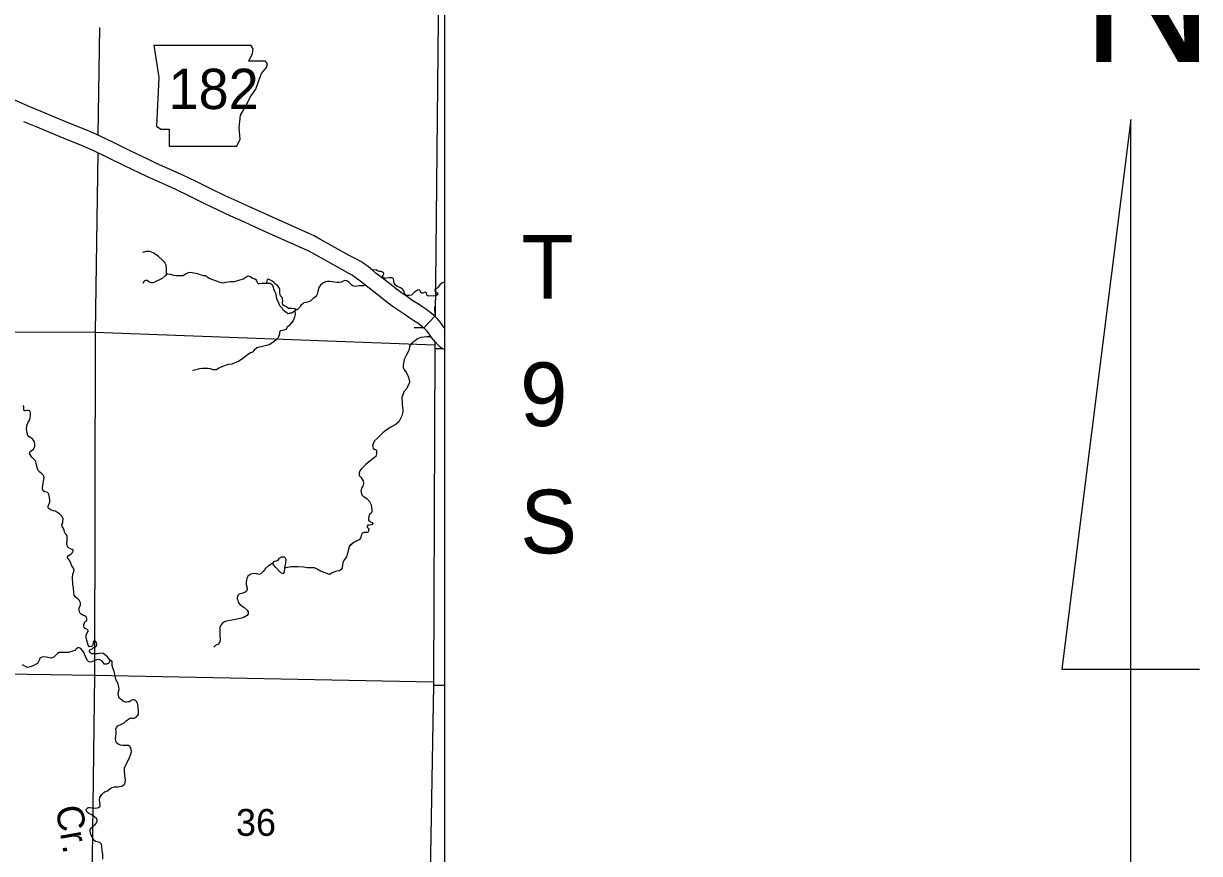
# Model space of a CAD drawing. Extents: x 8749 to 11879, y 13275 to 15339.
# Drawn here: x 10827.5 to 11197, y 14014.5 to 14275.3 of the extents above; entities that cross this region are included whole.
import ezdxf

# ---------------------------------------------------------------- set-up
doc = ezdxf.new("R2010")
doc.units = 0
for name, color, linetype in [('Level 10', 7, 'Continuous'), ('Level 21', 7, 'Continuous'), ('Level 35', 7, 'Continuous'), ('Level 37', 7, 'Continuous'), ('Level 4', 7, 'Continuous'), ('Level 5', 7, 'Continuous'), ('R_Draft', 7, 'Continuous')]:
    doc.layers.add(name, color=color, linetype=linetype)

msp = doc.modelspace()

# ---------------------------------------------------------------- linework, layer by layer
at = {"layer": 'Level 10'}
msp.add_line((10934.16, 14200.04), (10934.13, 14200.06), dxfattribs=at)
for points in [[(10829.51, 14249.1), (10825.17, 14251.01), (10819.52, 14253.48), (10816.27, 14255.03), (10810.76, 14257.54), (10799.85, 14262.61)], [(10934.13, 14200.06), (10933.48, 14200.51), (10932.12, 14201.21), (10929.79, 14202.45), (10925.33, 14204.94), (10920.85, 14207.48), (10918.81, 14208.61), (10916.91, 14209.41), (10909.69, 14212.62), (10905.7, 14214.42), (10902.28, 14215.98), (10898.66, 14217.62), (10894.6, 14219.43), (10890.89, 14221.18), (10886.09, 14223.48), (10881.79, 14225.62), (10877.39, 14227.73), (10872.88, 14229.79), (10869.32, 14231.35), (10866.32, 14232.74), (10861.04, 14235.3), (10856.14, 14237.66), (10851.37, 14240.02), (10847.57, 14241.67), (10842.09, 14243.9), (10837.58, 14245.78), (10833.04, 14247.62), (10829.46, 14249.12)], [(10827.53, 14244.51), (10831.14, 14243), (10835.68, 14241.16), (10840.18, 14239.28), (10845.63, 14237.06), (10849.27, 14235.49), (10853.95, 14233.17), (10858.86, 14230.8), (10864.18, 14228.23), (10867.26, 14226.79), (10870.83, 14225.22), (10875.27, 14223.2), (10879.59, 14221.12), (10883.9, 14218.99), (10888.74, 14216.66), (10892.52, 14214.88), (10896.61, 14213.05), (10900.22, 14211.42), (10903.63, 14209.87), (10907.65, 14208.06), (10914.92, 14204.82), (10916.62, 14204.1), (10918.4, 14203.12), (10922.88, 14200.58), (10927.4, 14198.06), (10929.8, 14196.78), (10930.91, 14196.21), (10931.29, 14195.94)], [(10956.72, 14183.3), (10955.56, 14184.31), (10954.24, 14185.31), (10952.92, 14186.19), (10951.63, 14187.06), (10949.82, 14188.2), (10948.1, 14189.39), (10946.28, 14190.68), (10944.68, 14191.87), (10943.02, 14193.14), (10941.63, 14194.24), (10940.7, 14195.02), (10939.07, 14196.23), (10938.34, 14196.78), (10937.26, 14197.69), (10936.41, 14198.38), (10935.46, 14199.12), (10934.16, 14200.04)], [(10931.27, 14195.96), (10932.47, 14195.11), (10933.3, 14194.46), (10934.07, 14193.84), (10935.21, 14192.87), (10936.07, 14192.22), (10937.59, 14191.09), (10938.47, 14190.36), (10939.95, 14189.19), (10941.68, 14187.87), (10943.34, 14186.63), (10945.23, 14185.29), (10947.06, 14184.03), (10948.9, 14182.86), (10950.14, 14182.03), (10951.34, 14181.24), (10953.25, 14179.7)], [(10953.25, 14179.7), (10956.72, 14183.3)], [(10959.72, 14179.64), (10959.71, 14179.65), (10958.83, 14180.88), (10958.19, 14181.72), (10957.48, 14182.57), (10956.72, 14183.3)], [(10959.72, 14172.87), (10959.26, 14173.09), (10958.31, 14173.75), (10957.84, 14174.15), (10956.91, 14175.14), (10955.73, 14176.62), (10954.81, 14177.9), (10954.27, 14178.6), (10953.81, 14179.16), (10953.25, 14179.7)]]:
    msp.add_lwpolyline(points, dxfattribs=at)
at = {"layer": 'Level 21'}
for p, q in [((10868.47, 14268.54), (10869.99, 14258.39)), ((10898.24, 14263.47), (10899.43, 14265.84)), ((10899.6, 14267.36), (10898.9, 14268.53)), ((10899.43, 14265.84), (10899.6, 14267.36)), ((10903.49, 14263.47), (10898.24, 14263.47)), ((10904.17, 14262.62), (10903.49, 14263.47)), ((10903.83, 14261.44), (10904.17, 14262.62)), ((10869.99, 14258.39), (10869.31, 14243)), ((10901.46, 14257.38), (10902.3, 14259.58)), ((10902.3, 14259.58), (10903.83, 14261.44)), ((10898.75, 14252.13), (10900.44, 14254.67)), ((10900.44, 14254.67), (10901.46, 14257.38)), ((10897.57, 14249.76), (10898.75, 14252.13)), ((10895.71, 14246.55), (10897.57, 14249.76)), ((10895.2, 14242.49), (10895.71, 14246.55)), ((10869.31, 14243), (10870.67, 14242.15)), ((10870.67, 14242.15), (10873.21, 14242.15)), ((10873.21, 14242.15), (10873.21, 14236.74)), ((10895.54, 14238.94), (10895.2, 14242.49)), ((10873.21, 14236.74), (10894.52, 14236.74)), ((10894.52, 14236.74), (10895.54, 14238.94))]:
    msp.add_line(p, q, dxfattribs=at)
msp.add_lwpolyline([(10868.47, 14268.54), (10898.9, 14268.53)], dxfattribs=at)
at = {"layer": 'Level 35'}
for points in [[(10872.4, 14196.52), (10872.45, 14197.58), (10872.47, 14198.44), (10872.35, 14199.32), (10871.89, 14200.2), (10871.34, 14200.76), (10869.88, 14202.09), (10868.27, 14203.28), (10867.23, 14203.68), (10866.07, 14203.63), (10864.89, 14203.35)], [(10881.66, 14196.7), (10880.44, 14197), (10879.86, 14197.02), (10879.18, 14196.97), (10878.34, 14196.49), (10877.69, 14196.06), (10876.33, 14196.01), (10875.42, 14196.04), (10874.72, 14196.14), (10873.66, 14196.47), (10872.85, 14196.54), (10872.4, 14196.52), (10871.97, 14196.01), (10871.11, 14195.16), (10870.26, 14194.73), (10869.45, 14194.4), (10868.27, 14193.85), (10867.61, 14193.85), (10866.86, 14194.17), (10866.35, 14194.53), (10865.82, 14194.58), (10865.37, 14194.35), (10864.97, 14193.59)], [(10896.5, 14194.99), (10895.02, 14194.6), (10893.71, 14194.17), (10892.55, 14194.1), (10891.67, 14194.05), (10890.88, 14193.95), (10890.1, 14193.74), (10889.25, 14193.9), (10886.95, 14194.73), (10885.87, 14195.13), (10885.47, 14195.36), (10885.04, 14195.81), (10884.69, 14195.99), (10884.06, 14196.06), (10883.3, 14196.27), (10882.27, 14196.62), (10881.66, 14196.7)], [(10914.46, 14186.52), (10914.19, 14186.04), (10913.81, 14185.66), (10913.43, 14185.36), (10913.2, 14185.33), (10912.77, 14185.66), (10911.79, 14185.74), (10910.78, 14185.79), (10910.1, 14186.24), (10909.6, 14186.52), (10909, 14186.9), (10908.87, 14187.58), (10908.94, 14188.31), (10908.77, 14189.17), (10908.26, 14189.77), (10908.04, 14190.58), (10908.04, 14191.16), (10908.06, 14191.69), (10907.79, 14192.24), (10907.28, 14192.98), (10906.7, 14193.35), (10906.17, 14193.96), (10905.57, 14194.31), (10904.89, 14194.77), (10904.33, 14194.94), (10904.23, 14194.92), (10904.08, 14194.79), (10903.96, 14194.31), (10903.88, 14193.88), (10903.58, 14193.68), (10903.2, 14193.56), (10902.34, 14193.58), (10901.69, 14193.45), (10901.21, 14193.5), (10900.93, 14194.11), (10900.73, 14194.67), (10900.18, 14194.97), (10899.4, 14195.14), (10898.79, 14195.65), (10898.31, 14195.9), (10897.73, 14195.83), (10896.98, 14195.25), (10896.5, 14194.99)], [(10938.31, 14197.9), (10937.19, 14197.75)], [(10945.48, 14192.42), (10944.94, 14192.71), (10944.27, 14193.18), (10943.99, 14193.73), (10943.87, 14194.48), (10943.72, 14195.03), (10943.48, 14195.3), (10943.14, 14195.37), (10942.41, 14195.36), (10941.68, 14195.27), (10940.98, 14195.17), (10940.52, 14195.44), (10940.33, 14195.74), (10940.4, 14196.13), (10940.58, 14196.37), (10940.67, 14196.7), (10940.58, 14196.94), (10940.31, 14197.15), (10939.86, 14197.33), (10939.24, 14197.38), (10938.71, 14197.58), (10938.31, 14197.9)], [(10913.43, 14185.36), (10912.7, 14185.13), (10912.27, 14184.6), (10911.82, 14184.3), (10911.24, 14184.25), (10910.63, 14184.1), (10909.98, 14184.45), (10909.22, 14185.11), (10908.82, 14185.71), (10908.06, 14186.57), (10907.74, 14187.4), (10907.06, 14188.81), (10906.88, 14190.25), (10906.43, 14191.11), (10906.15, 14191.79), (10906.05, 14192.47), (10905.62, 14193.15), (10904.96, 14193.58), (10903.2, 14193.56)], [(10929.85, 14193.89), (10929.43, 14194.26), (10929.07, 14194.49), (10928.44, 14194.55), (10927.9, 14194.39), (10927.25, 14194.06), (10926.64, 14193.94), (10925.99, 14193.95), (10923.77, 14194.26), (10922.98, 14194.28), (10922.33, 14194.15), (10921.51, 14193.66), (10920.78, 14193.13), (10920.46, 14192.69), (10920.19, 14192.11), (10919.95, 14191.04)], [(10935, 14193.05), (10934.36, 14192.85), (10933.64, 14192.85), (10932.93, 14192.88), (10932.32, 14192.78), (10931.74, 14192.7), (10931.06, 14192.78), (10930.6, 14193.1), (10930.23, 14193.52), (10929.85, 14193.89)], [(10951.26, 14191.52), (10950.35, 14190.86), (10949.82, 14190.31), (10949.38, 14189.92), (10948.68, 14189.82), (10948.19, 14189.81), (10947.69, 14189.86), (10947.4, 14190.04), (10947.15, 14190.55), (10946.99, 14191.26), (10946.76, 14191.62), (10946.42, 14191.96), (10945.96, 14192.25), (10945.48, 14192.42)], [(10959.72, 14193.95), (10959.38, 14193.94), (10958.94, 14193.69), (10958.32, 14193.17), (10957.76, 14192.5), (10957.32, 14192.08), (10956.99, 14191.95), (10956.86, 14191.82), (10956.76, 14191.63), (10956.71, 14191.47), (10956.71, 14191.33), (10956.81, 14191.15), (10957.11, 14190.9), (10957.5, 14190.66), (10957.68, 14190.36), (10957.5, 14190.02), (10957.1, 14189.88), (10956.18, 14189.67), (10955.5, 14189.68), (10954.87, 14189.64), (10954.56, 14189.7), (10954.23, 14189.99), (10954.1, 14190.42), (10953.96, 14190.66), (10953.7, 14190.85), (10953.35, 14190.83), (10952.93, 14190.59), (10952.62, 14190.59), (10952.38, 14190.79), (10952.23, 14191.15), (10951.95, 14191.48), (10951.58, 14191.61), (10951.26, 14191.52)], [(10919.95, 14191.04), (10919.78, 14190.25), (10919.6, 14189.79), (10919.24, 14189.39), (10918.47, 14188.93), (10917.74, 14188.21), (10916.68, 14187.7), (10916.16, 14187.67), (10915.56, 14187.53), (10915.12, 14187.16), (10914.65, 14186.75), (10914.46, 14186.52)], [(10912.7, 14185.13), (10912.8, 14183.88), (10912.6, 14183.02), (10912.22, 14181.91), (10911.54, 14181.13), (10910.84, 14180.35), (10910.38, 14179.9), (10910.08, 14179.42), (10909.9, 14179.14), (10909.38, 14178.91), (10908.8, 14178.81), (10908.24, 14178.76), (10907.99, 14178.51), (10907.91, 14178.16), (10907.94, 14177.78), (10907.74, 14177.1), (10907.36, 14176.42), (10906.81, 14175.79), (10905.8, 14175.05), (10904.64, 14174.35), (10903, 14173.92), (10900.83, 14173.39), (10899.93, 14172.61), (10899.45, 14172.08), (10898.77, 14171.78), (10897.76, 14171.12)], [(10955.6, 14176.8), (10954.31, 14176.81), (10953.35, 14176.79), (10952.37, 14176.66), (10951.24, 14176.21), (10950.56, 14175.63), (10949.57, 14175), (10948.84, 14174.16), (10948.74, 14173.56), (10948.51, 14172.6)], [(10897.76, 14171.12), (10896.26, 14169.93), (10895.15, 14169.15), (10892.99, 14168.24), (10891.8, 14168.17), (10890.06, 14167.53), (10888.85, 14167.01), (10888.17, 14166.45), (10887.44, 14166.43), (10886.96, 14166.48), (10886.21, 14166.75), (10885.5, 14166.88), (10884.85, 14166.9), (10883.61, 14166.93), (10882.76, 14166.78), (10881.24, 14166.32), (10880.56, 14166.12)], [(10948.51, 14172.6), (10947.78, 14171.22), (10947.13, 14169.71), (10946.93, 14168.52), (10946.75, 14167.74), (10946.78, 14167.19), (10947.05, 14166.48), (10947.71, 14165.73), (10948.49, 14164.19)], [(10948.49, 14164.19), (10948.77, 14162.79), (10948.72, 14162.36), (10948.39, 14161.71), (10947.94, 14160.65), (10946.98, 14159.59), (10946.73, 14158.93), (10946.37, 14157.92), (10946.32, 14157.27), (10946.47, 14156.33), (10946.5, 14155.44), (10946.6, 14154.78), (10946.71, 14153.9), (10946.68, 14153.27), (10946.4, 14151.97), (10945.97, 14151.21)], [(10829.57, 14153.36), (10829.24, 14153.69), (10828.84, 14153.72), (10828.51, 14153.67), (10828.03, 14153.59), (10827.85, 14153.62), (10827.62, 14153.79), (10827.57, 14154.15), (10827.6, 14154.45), (10827.62, 14154.98), (10827.4, 14155.31)], [(10830.93, 14138.16), (10830.15, 14139), (10829.7, 14139.65), (10829.37, 14140.21), (10829.57, 14140.82), (10830.6, 14141.58), (10831.08, 14142.36), (10831.08, 14143.04), (10830.96, 14143.88), (10830.28, 14144.81), (10829.32, 14145.44), (10828.79, 14146.05), (10828.61, 14146.83), (10828.46, 14147.85), (10828.58, 14148.98), (10829.09, 14150.2), (10829.47, 14150.78), (10829.62, 14151.39), (10829.72, 14152.04), (10829.67, 14152.75), (10829.57, 14153.36)], [(10945.97, 14151.21), (10945.37, 14150.09), (10944.56, 14149.44), (10942.93, 14148.43), (10941.44, 14147.47), (10940.38, 14146.64), (10939.5, 14145.88), (10938.72, 14144.97), (10937.81, 14144.14), (10937.33, 14143.23), (10937.16, 14142.65), (10937.31, 14141.82)], [(10937.31, 14141.82), (10937.61, 14141.56), (10938.04, 14141.49), (10938.37, 14141.19), (10938.42, 14140.86), (10938.42, 14140.05), (10938.16, 14139.24), (10937.21, 14138.46), (10935.87, 14137.5), (10935.01, 14136.7), (10934.23, 14135.86), (10933.55, 14135.31), (10933.13, 14134.75), (10932.97, 14134.07), (10932.97, 14133.32), (10933.43, 14132.71), (10934.16, 14131.6), (10934.28, 14130.72), (10934.13, 14129.96), (10933.73, 14129.28), (10933.5, 14128.45), (10933.58, 14127.9), (10933.81, 14127.24), (10934.26, 14126.79), (10935.37, 14126.03)], [(10835.28, 14123.07), (10835.25, 14123.59), (10835.4, 14124.2), (10835.78, 14124.86), (10835.8, 14125.77), (10835.58, 14126.83), (10835.45, 14127.26), (10835.1, 14127.94), (10834.21, 14128.19), (10833.66, 14128.47), (10833.48, 14129.08), (10833.53, 14130.24), (10833.96, 14132.67), (10833.93, 14133.2), (10833.3, 14133.81), (10832.6, 14134.29), (10832.09, 14134.82), (10831.69, 14136.11), (10831.48, 14137.17), (10831.33, 14137.73), (10830.93, 14138.16)], [(10935.37, 14126.03), (10936.22, 14125.07), (10936.68, 14124.01), (10936.96, 14122.52), (10936.98, 14121.87), (10936.73, 14121.46), (10936.22, 14121.03), (10935.95, 14120.25), (10935.92, 14119.75), (10935.92, 14119.24), (10936.53, 14118.76), (10937.01, 14118.54), (10937.23, 14118.18), (10937.16, 14117.91), (10936.88, 14117.73), (10936.2, 14117.68), (10935.7, 14117.65), (10935.47, 14117.4), (10935.49, 14117.02), (10935.95, 14116.47), (10935.92, 14115.94), (10935.82, 14115.59), (10935.52, 14115.33), (10934.81, 14115.36), (10934.41, 14115.36), (10933.83, 14115.08), (10933.65, 14114.65), (10933.38, 14113.53), (10933, 14113.05), (10932.22, 14112.73), (10931.01, 14112.04), (10930.13, 14111.21)], [(10841.13, 14111.79), (10841.16, 14112.79), (10841.18, 14113.37), (10841.26, 14113.78), (10841.23, 14114.06), (10840.96, 14114.59), (10840.55, 14115.02), (10840.4, 14115.5), (10840.32, 14116.08), (10840.02, 14116.61), (10839.62, 14117.27), (10839.57, 14117.9), (10839.87, 14118.35), (10839.87, 14118.91), (10839.92, 14119.67), (10839.79, 14120.15), (10839.44, 14120.63), (10838.81, 14121.19), (10837.47, 14122.05), (10836.86, 14122.22), (10836.43, 14122.37), (10835.93, 14122.48), (10835.47, 14122.86), (10835.28, 14123.07)], [(10843.17, 14097.73), (10842.95, 14099.18), (10842.85, 14101.07), (10843, 14102.26), (10843.28, 14103.07), (10843.38, 14103.63), (10843.25, 14104.16), (10842.65, 14104.89), (10842.27, 14105.98), (10842.07, 14106.48), (10841.74, 14106.86), (10841.33, 14107.32), (10841.31, 14107.67), (10841.56, 14107.98), (10842.09, 14108.31), (10842.52, 14108.66), (10842.93, 14109.04), (10843.1, 14109.52), (10843.05, 14109.82), (10842.88, 14110), (10842.22, 14110.25), (10841.56, 14110.63), (10841.26, 14111.24), (10841.13, 14111.79)], [(10931.01, 14112.04), (10929.95, 14111.16), (10929.73, 14110.48), (10929.52, 14109.67), (10929.3, 14108.76), (10928.95, 14107.73), (10928.27, 14106.79), (10927.84, 14105.86), (10927.76, 14105.16), (10927.58, 14104.3), (10927.28, 14103.77), (10926.75, 14103.29), (10925.87, 14103.16), (10924.64, 14102.79), (10923.67, 14102.2)], [(10909.48, 14104.25), (10909.35, 14102.95), (10909.18, 14102.5), (10908.98, 14102.4), (10908.27, 14102.77), (10906.78, 14104.36), (10906.03, 14105.22), (10905.8, 14105.73), (10906.23, 14106.26), (10907.51, 14106.71)], [(10907.51, 14106.71), (10907.92, 14107.31), (10908.62, 14107.72), (10909.05, 14107.72), (10909.4, 14107.69), (10909.66, 14107.44), (10909.96, 14106.96), (10909.83, 14105.75), (10909.48, 14104.25)], [(10905.8, 14105.73), (10904.47, 14104.84), (10903.41, 14103.94), (10902.75, 14103.13), (10902.05, 14102.42), (10901.55, 14102.19), (10900.76, 14102.37), (10899.76, 14102.47), (10898.95, 14102.25), (10897.99, 14101.67), (10897.61, 14100.93), (10897.49, 14099.82), (10897.46, 14098.97), (10897.72, 14097.91), (10897.77, 14097.45), (10897.51, 14096.92), (10897.04, 14096.55), (10896.13, 14096.24), (10895.27, 14095.97), (10894.87, 14095.56), (10894.62, 14094.98), (10894.62, 14094.55), (10894.84, 14094.05), (10894.89, 14093.42), (10895.6, 14092.61), (10896.71, 14091.86), (10897.77, 14090.98)], [(10923.67, 14102.2), (10920.84, 14103.18), (10919.75, 14103.83), (10918.92, 14104.21), (10917.64, 14104.26), (10916.65, 14104.24), (10915.47, 14104.49), (10913.73, 14104.57), (10912.25, 14104.62), (10911.54, 14104.57), (10909.93, 14104.26), (10909.48, 14104.25)], [(10847.19, 14083.14), (10847.52, 14083.85), (10847.77, 14084.21), (10847.77, 14084.59), (10847.37, 14084.96), (10846.89, 14085.19), (10846.53, 14085.57), (10846.46, 14085.98), (10846.48, 14086.43), (10846.63, 14086.94), (10846.79, 14087.29), (10847.34, 14087.72), (10847.39, 14088.25), (10847.32, 14088.66), (10847.16, 14088.91), (10846.81, 14089.16), (10846.18, 14089.39), (10845.65, 14089.69), (10845.19, 14090.12), (10844.97, 14090.91), (10844.94, 14091.61), (10845.37, 14092.6), (10845.35, 14093.23), (10845.17, 14093.71), (10844.94, 14094.14), (10844.54, 14094.47), (10844.18, 14094.8), (10843.73, 14095.18), (10843.38, 14095.71), (10843.32, 14096.54), (10843.17, 14097.73)], [(10897.77, 14090.98), (10898.07, 14090.4), (10898.09, 14089.8), (10897.72, 14089.27), (10896.51, 14088.51), (10893.61, 14087.96), (10891.32, 14087.5), (10890.69, 14087.28), (10890.06, 14086.82), (10889.48, 14086.27), (10889.17, 14085.54), (10889.17, 14083.32)], [(10849.99, 14081.29), (10849.59, 14081.21), (10849.41, 14080.86), (10849.31, 14080.28), (10849.24, 14079.98), (10848.88, 14079.57), (10848.2, 14079.44), (10847.8, 14079.98), (10847.49, 14081.09), (10847.19, 14082.23), (10847.19, 14083.14)], [(10854.69, 14075.14), (10853.86, 14076.26), (10852.97, 14076.99), (10852.52, 14077.37), (10851.79, 14077.45), (10850.88, 14077.27), (10850.14, 14077.27), (10849.31, 14077.22), (10848.88, 14077.22), (10848.45, 14077.65), (10848.25, 14077.95), (10848.28, 14078.23), (10848.33, 14078.48), (10848.58, 14078.64), (10848.96, 14078.71), (10849.39, 14079.09), (10850.12, 14079.55), (10850.5, 14079.85), (10850.55, 14080.25), (10850.47, 14080.68), (10850.22, 14081.06), (10849.99, 14081.29), (10849.82, 14081.37)], [(10889.17, 14083.32), (10889.23, 14081.5), (10889.05, 14080.84), (10888.65, 14080.28), (10887.84, 14079.83), (10887.28, 14079.34)], [(10841.66, 14077.7), (10838.71, 14077.65), (10838.18, 14077.32), (10837.1, 14076.31), (10836.14, 14075.9), (10834.57, 14076.21), (10833.84, 14076.31), (10833.21, 14076.18), (10832.65, 14075.85), (10832.45, 14075.25), (10832.15, 14074.66), (10831.84, 14074.23), (10831.29, 14073.83), (10830.58, 14073.45), (10829.55, 14073.15), (10828.76, 14072.89), (10828.08, 14073.2), (10827.22, 14073.75)], [(10856.23, 14070.83), (10855.96, 14071.71), (10855.53, 14072.84), (10855.4, 14073.53), (10855.35, 14074.26), (10855.32, 14074.79), (10855.02, 14075.17), (10854.69, 14075.14), (10854.54, 14074.84), (10854.24, 14074.23), (10853.53, 14074.01), (10852.95, 14073.98), (10852.55, 14074.49), (10852.17, 14074.92), (10851.43, 14075.3), (10850.75, 14075.45), (10849.94, 14075.14), (10849.21, 14074.79), (10848.45, 14074.64), (10847.97, 14074.69), (10847.52, 14075.22), (10846.94, 14076.36), (10846.36, 14077.87), (10845.55, 14078.89), (10845.02, 14079.14), (10844.54, 14079.09), (10843.96, 14078.66), (10843.58, 14078.28), (10843, 14078.03), (10841.66, 14077.7)], [(10857.52, 14066.07), (10857.42, 14066.91), (10857.19, 14067.72), (10856.46, 14069.31), (10856.33, 14070.25), (10856.23, 14070.83)], [(10860.43, 14056.75), (10861.06, 14057.09), (10861.44, 14056.99), (10862.25, 14056.99), (10862.9, 14057.35), (10863.58, 14058.2), (10863.66, 14059.27), (10863.56, 14060.48), (10863.41, 14061.34), (10863.08, 14062.17), (10862.73, 14062.55), (10862.27, 14062.76), (10861.87, 14062.76), (10861.31, 14062.55), (10860.81, 14062.17), (10860.35, 14062.12), (10859.97, 14062.05), (10859.49, 14062.07), (10859.11, 14062.12), (10858.81, 14062.38), (10858.28, 14062.73), (10857.7, 14063.21), (10857.42, 14063.67), (10857.24, 14064.47), (10857.32, 14065.36), (10857.52, 14066.07)], [(10861.08, 14045.49), (10861.39, 14046.46), (10861.34, 14047.42), (10860.88, 14048.16), (10860.48, 14048.41), (10859.49, 14048.46), (10858.66, 14048.43), (10857.95, 14048.51), (10857.09, 14048.99), (10856.56, 14049.6), (10856.41, 14050.46), (10856.61, 14052.18), (10856.56, 14052.96), (10856.54, 14053.59), (10856.66, 14054.1), (10857.14, 14054.58), (10858.3, 14055.08), (10859.24, 14055.66), (10859.87, 14056.25), (10860.43, 14056.75)], [(10853.91, 14034.18), (10854.77, 14034.87), (10855.35, 14035.18), (10856.06, 14035.4), (10857.17, 14035.43), (10857.8, 14035.53), (10858.56, 14035.78), (10859.32, 14036.34), (10859.54, 14037.58), (10859.34, 14038.97), (10859.26, 14040.61), (10859.24, 14041.55), (10859.95, 14042.84), (10860.81, 14044.68), (10861.08, 14045.49)], [(10848.45, 14022.04), (10848.76, 14022.5), (10849.44, 14023.18), (10850.02, 14023.59), (10850.58, 14024.27), (10850.63, 14024.88), (10850.4, 14025.48), (10849.79, 14026.06), (10848.98, 14026.65), (10848.05, 14027.05), (10847.49, 14027.5), (10847.17, 14028.11), (10847.27, 14028.41), (10847.77, 14028.9), (10848.23, 14028.95), (10849.09, 14028.79), (10850.2, 14028.69), (10851.01, 14028.9), (10851.54, 14029.38), (10851.61, 14029.81), (10851.38, 14031.22), (10851.51, 14032.11), (10852.14, 14033.02), (10852.77, 14033.7), (10853.2, 14034), (10853.91, 14034.18)], [(10852.39, 14012.72), (10852.37, 14014.25), (10852.22, 14015.46), (10852.14, 14016.75), (10852.02, 14017.46), (10851.43, 14017.97), (10850.65, 14018.17), (10850.1, 14018.29), (10849.54, 14018.67), (10848.73, 14020.22), (10848.56, 14020.9), (10848.48, 14021.66), (10848.45, 14022.04)]]:
    msp.add_lwpolyline(points, dxfattribs=at)
at = {"layer": 'Level 37'}
for points in [[(10956.67, 14186.3), (10956.72, 14183.3)], [(10953.25, 14179.7), (10950.25, 14179.65)]]:
    msp.add_lwpolyline(points, dxfattribs=at)
at = {"layer": 'Level 4'}
for points in [[(10958, 14309.51), (10957.85, 14279.31), (10957.82, 14276.65), (10956.82, 14183.21)], [(10956.73, 14175.33), (10956.72, 14174.36), (10956.72, 14173.18), (10956.28, 14068.43), (10956.27, 14067.4), (10954.85, 13984.45)]]:
    msp.add_lwpolyline(points, dxfattribs=at)
at = {"layer": 'Level 5'}
for points in [[(10851.36, 14274.1), (10850.89, 14240.24)], [(10850.81, 14234.72), (10850.02, 14178.33)], [(10744.74, 14178.51), (10850.02, 14178.33)], [(10850.02, 14178.33), (10849.81, 14070.52)], [(10850.02, 14178.33), (10956.72, 14174.36)], [(10956.72, 14173.18), (10959.2, 14173.14)], [(10744.14, 14072.12), (10849.81, 14070.52)], [(10849.81, 14070.52), (10848.41, 13963.94)], [(10849.81, 14070.52), (10956.28, 14068.43)], [(10956.27, 14067.4), (10959.72, 14067.34)]]:
    msp.add_lwpolyline(points, dxfattribs=at)
at = {"layer": 'R_Draft'}
for p, q in [((11175.37, 14245.18), (11153.77, 14072.38)), ((11175.37, 13964.38), (11175.37, 14245.18)), ((11153.77, 14072.38), (11196.97, 14072.38))]:
    msp.add_line(p, q, dxfattribs=at)
msp.add_lwpolyline([(9678.09, 14456.3), (10959.72, 14456.3), (10959.72, 13439.87), (9678.09, 13439.87)], close=True, dxfattribs=at)

# ---------------------------------------------------------------- texts
at = {"layer": 'Level 21'}
msp.add_text('182', height=12.672, dxfattribs=at).set_placement((10873.09, 14248.42))
at = {"layer": 'Level 35'}
msp.add_text('Cr.', height=8.448, rotation=280.0714, dxfattribs=at).set_placement((10837.51, 14028.9))
at = {"layer": 'Level 5'}
msp.add_text('36', height=8.448, dxfattribs=at).set_placement((10894.25, 14020.03))
at = {"layer": 'R_Draft'}
for s, height, p in [('N', 43.2, (11159.77, 14263.18)), ('T', 20, (10983.98, 14188.8)), ('9', 20, (10983.51, 14148.8)), ('S', 20, (10983.56, 14108.8))]:
    msp.add_text(s, height=height, dxfattribs=at).set_placement(p)

doc.saveas('drawing.dxf')
